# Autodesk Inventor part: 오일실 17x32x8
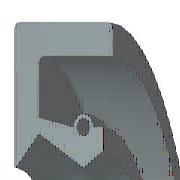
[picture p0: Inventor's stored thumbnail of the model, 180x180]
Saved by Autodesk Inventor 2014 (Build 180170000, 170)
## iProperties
IsCustomPart: 1
Created: 2009-02
Part Number: 오일실 17x32x8
Material: 고무
Description: 오일-실
Document SubType Name: Modeling
Standard: KS B 2804
Designer: 한국산업디자인학원
Standards Organization: KS
Language: ko-KR
Size Designation: D - 17 32 8
Categories: <MemberInstance><Categories><Category DisplayName="샤프트 부품" InternalName="7f7aeb1f-a693-4053-b835-cee3144e0d98" Mnemonic="SHFT"><Category DisplayName="실링" Intern
Density: 0.93 g/cm^3
Appearance: 고무 - 검은색 - 버전 1.1
Author: 한국산업디자인학원
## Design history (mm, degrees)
revolve "본체" stored, may be unused: angle "d17" = 90 deg
revolve "스프링1" stored, may be unused: angle "d18" = 90 deg
body "Solid1"
sketch "스케치1"
  geometry: L1 (0, 16)-(8, 16); L2 (8, 14.25)-(1.75, 14.25); L3 (1.75, 10.25)-(4.9, 8.5); L4 (4.9, 8.5)-(0, 8.5); L5 (0, 0)-(9.586, 0) reference; L6 (4.9, 8.5)-(6.3, 9.375); L7 (0, 18)-(0, -3) reference; L8 (-1.941, 0)-(11.507, 0) reference; L9 (4.2, 10.6)-(1.75, 11.21); L10 (1.75, 11.21)-(1.75, 14.25); L11 (0, 16)-(0, 8.588); L12 (4.9, 8.5)-(0, 8.5); L13 (1.75, 10.25)-(0.152, 8.528); L14 (8, 16)-(8, 14.25); L15 (5.6, 10.6)-(6.3, 10.6); L16 (6.3, 10.6)-(6.3, 9.375); C1 r 0.455 at (4.9, 10.6); A1 r 0.7 centre (4.9, 10.6) between (5.6, 10.6) and (4.2, 10.6); A2 r 0.088 centre (0.088, 8.588) between (0, 8.588) and (0.152, 8.528); 1 further point
  constraints: 28 end point, 5 horizontal alignment, 5 point on line, 4 point on circle, 4 vertical alignment, 3 centre point, 3 tangent, 2 collinear, 2 horizontal, 2 perpendicular, 1 coincident, 1 parallel
  dimensions: "d0" = 32 diameter of L1 L5 (= SD2); "d1" = 1.75 distance of L1.end L2.start (= SD); "d2" = 0.91 diameter of C1 (= SPDI); "d3" = 1.4 diameter of A1 (= SPDA); "d4" = 17 diameter of L3.end L5 (= NND); "d5" = 20.5 diameter of L3.start L5 (= TKDM); "d7" = 22.42 diameter of L9.end L5 (= TKDM + 0.24 x SWDT); "d8" = 1.75 distance between parallel lines of L11 L10 (= SD); "d9" = 4.9 distance from line of L11 C1.centre (= SPDST); "d10" = 21.2 diameter of C1.centre L5 (= HLDM); "d11" = 0.0875 radius of A2 (= 0.25 x LAB); "d12" = 6.3 distance between parallel lines of L11 L16 (= SDI); "d13" = 18.75 diameter of L6.end L5 (= ABDM); "d14" = 8 distance from line of L11 L1.end (= SWDT)
fillet "모깎기1" dims "d6" = 0.3 (= RR)
other parameters: "SD2" = 32 [user parameter; used in 1 equation term], "SWDT" = 8 [user parameter; used in 2 equation terms], "RR" = 0.3 [user parameter; used in 1 equation term], "SD" = 1.75 [user parameter; used in 2 equation terms], "NND" = 17 [user parameter; used in 1 equation term], "SPDA" = 1.4 [user parameter; used in 1 equation term], "SPDI" = 0.91 [user parameter; used in 1 equation term], "TKDM" = 20.5 [user parameter; used in 2 equation terms], "HLDM" = 21.2 [user parameter; used in 1 equation term], "ABDM" = 18.75 [user parameter; used in 1 equation term], "SDI" = 6.3 [user parameter; used in 1 equation term], "SPDST" = 4.9 [user parameter; used in 1 equation term], "LAB" = 0.35 [user parameter; used in 1 equation term], "d15" = 0, "d16" = 0, "d19" = 0
